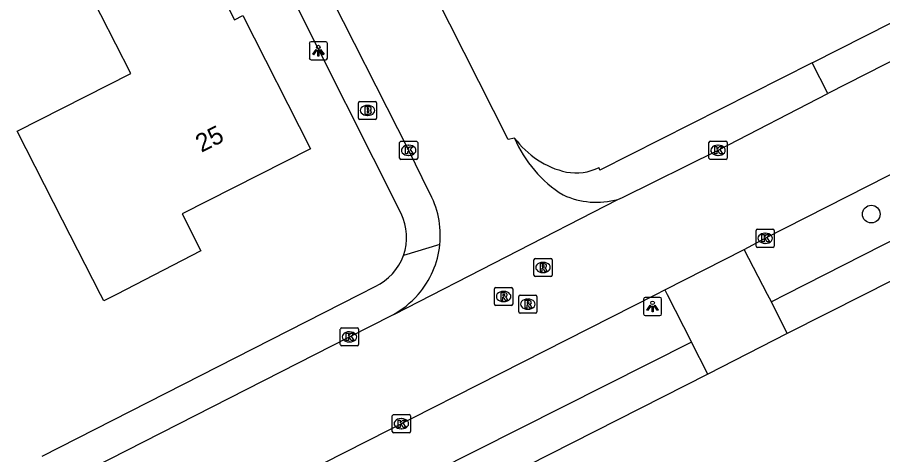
# Model space of a CAD drawing. Extents: x 162722 to 165099, y 384721 to 386283.
# Drawn here: x 164013.51 to 164061.27, y 384991.16 to 385015.28 of the extents above; entities that cross this region are included whole.
import ezdxf

# ---------------------------------------------------------------- set-up
doc = ezdxf.new("R2010")
doc.units = 0
for name, color, linetype in [('IMGEO_Boom', 7, 'Continuous'), ('IMGEO_Brandkraan', 7, 'Continuous'), ('IMGEO_Kolk', 7, 'Continuous'), ('IMGEO_Lichtpunt', 7, 'Continuous'), ('IMGEO_Pand', 7, 'Continuous'), ('IMGEO_Pand_nummerreeks', 7, 'Continuous'), ('IMGEO_Parkeervlak_open', 7, 'Continuous'), ('IMGEO_Rijbaan_lokaal_open', 7, 'Continuous'), ('IMGEO_Rioolput', 7, 'Continuous'), ('IMGEO_Voetpad_open', 7, 'Continuous')]:
    doc.layers.add(name, color=color, linetype=linetype)

msp = doc.modelspace()

# ---------------------------------------------------------------- linework, layer by layer
at = {"layer": 'IMGEO_Boom'}
msp.add_circle((164060.638, 385004.427), 0.489, dxfattribs=at)
at = {"layer": 'IMGEO_Brandkraan'}
for p, q in [((164032.34, 385009.72), (164032.34, 385010.572)), ((164032.415, 385010.646), (164033.267, 385010.646)), ((164032.828, 385010.426), (164032.853, 385010.426)), ((164033.341, 385010.572), (164033.341, 385009.72)), ((164032.851, 385009.866), (164032.826, 385009.866)), ((164033.267, 385009.646), (164032.415, 385009.646))]:
    msp.add_line(p, q, dxfattribs=at)
for points in [[(164032.34, 385009.72), (164032.34, 385010.572)], [(164032.415, 385010.646), (164033.267, 385010.646)], [(164032.688, 385010.346), (164032.688, 385009.946), (164032.901, 385009.946)], [(164032.919, 385010.346), (164032.688, 385010.346)], [(164032.867, 385010.265), (164032.813, 385010.265), (164032.813, 385010.189)], [(164033.341, 385010.572), (164033.341, 385009.72)], [(164032.813, 385010.189), (164032.866, 385010.189)], [(164032.875, 385010.113), (164032.813, 385010.113), (164032.813, 385010.032)], [(164032.813, 385010.032), (164032.875, 385010.032)], [(164033.267, 385009.646), (164032.415, 385009.646)]]:
    msp.add_lwpolyline(points, dxfattribs=at)
for centre, radius, start, end in [((164032.417, 385010.57), 0.0765, 91.552, 178.448), ((164032.417, 385010.57), 0.0765, 91.552, 178.448), ((164032.868, 385010.227), 0.0379, 267.8285, 90.9355), ((164032.923, 385010.201), 0.145, 59.4692, 91.5367), ((164032.948, 385010.248), 0.0922, 285.5137, 58.1501), ((164033.265, 385010.57), 0.0765, 1.552, 88.448), ((164033.265, 385010.57), 0.0765, 1.552, 88.448), ((164032.876, 385010.072), 0.0404, 269.8759, 90.5077), ((164032.907, 385010.197), 0.251, 268.6676, 293.5347), ((164032.953, 385010.056), 0.105, 301.3115, 78.989), ((164032.417, 385009.722), 0.0765, 181.552, 268.448), ((164032.417, 385009.722), 0.0765, 181.552, 268.448), ((164033.265, 385009.722), 0.0765, 271.552, 358.448), ((164033.265, 385009.722), 0.0765, 271.552, 358.448)]:
    msp.add_arc(centre, radius, start, end, dxfattribs=at)
for centre, major_axis, ratio, start_param, end_param in [((164032.827, 385010.146), (-0.387, 0.002), 0.722429, 4.712389, 7.853982), ((164032.852, 385010.146), (-0.39, 0.002), 0.717154, 1.570796, 4.712389)]:
    msp.add_ellipse(centre, major_axis=major_axis, ratio=ratio, start_param=start_param, end_param=end_param, dxfattribs=at)
at = {"layer": 'IMGEO_Kolk'}
for p, q in [((164034.608, 385007.517), (164034.608, 385008.369)), ((164034.683, 385008.443), (164035.535, 385008.443)), ((164035.609, 385008.369), (164035.609, 385007.517)), ((164051.679, 385007.522), (164051.679, 385008.374)), ((164051.754, 385008.448), (164052.606, 385008.448)), ((164052.68, 385008.374), (164052.68, 385007.522)), ((164035.096, 385008.223), (164035.121, 385008.223)), ((164052.167, 385008.228), (164052.192, 385008.228)), ((164035.535, 385007.443), (164034.683, 385007.443)), ((164035.119, 385007.663), (164035.094, 385007.663)), ((164052.606, 385007.448), (164051.754, 385007.448)), ((164052.19, 385007.668), (164052.165, 385007.668)), ((164054.283, 385002.669), (164054.283, 385003.521)), ((164054.358, 385003.595), (164055.21, 385003.595)), ((164055.284, 385003.521), (164055.284, 385002.669)), ((164054.771, 385003.375), (164054.796, 385003.375)), ((164055.21, 385002.595), (164054.358, 385002.595)), ((164054.794, 385002.815), (164054.769, 385002.815)), ((164031.338, 384997.231), (164031.338, 384998.083)), ((164031.413, 384998.157), (164032.265, 384998.157)), ((164031.826, 384997.937), (164031.851, 384997.937)), ((164032.339, 384998.083), (164032.339, 384997.231)), ((164031.849, 384997.377), (164031.824, 384997.377)), ((164032.265, 384997.157), (164031.413, 384997.157)), ((164034.204, 384992.444), (164034.204, 384993.296)), ((164034.279, 384993.37), (164035.131, 384993.37)), ((164034.692, 384993.15), (164034.717, 384993.15)), ((164035.205, 384993.296), (164035.205, 384992.444)), ((164034.715, 384992.59), (164034.69, 384992.59)), ((164035.131, 384992.37), (164034.279, 384992.37))]:
    msp.add_line(p, q, dxfattribs=at)
for points in [[(164034.608, 385007.517), (164034.608, 385008.369)], [(164034.683, 385008.443), (164035.535, 385008.443)], [(164035.609, 385008.369), (164035.609, 385007.517)], [(164051.679, 385007.522), (164051.679, 385008.374)], [(164051.754, 385008.448), (164052.606, 385008.448)], [(164052.68, 385008.374), (164052.68, 385007.522)], [(164034.929, 385008.143), (164035.052, 385008.143), (164035.052, 385007.992), (164035.182, 385008.143), (164035.346, 385008.143), (164035.2, 385007.992), (164035.353, 385007.743), (164035.201, 385007.743), (164035.116, 385007.907), (164035.052, 385007.84), (164035.052, 385007.743), (164034.929, 385007.743), (164034.929, 385008.143)], [(164052, 385008.148), (164052.123, 385008.148), (164052.123, 385007.997), (164052.253, 385008.148), (164052.417, 385008.148), (164052.271, 385007.997), (164052.424, 385007.748), (164052.272, 385007.748), (164052.187, 385007.912), (164052.123, 385007.845), (164052.123, 385007.748), (164052, 385007.748), (164052, 385008.148)], [(164035.535, 385007.443), (164034.683, 385007.443)], [(164052.606, 385007.448), (164051.754, 385007.448)], [(164054.283, 385002.669), (164054.283, 385003.521)], [(164054.358, 385003.595), (164055.21, 385003.595)], [(164055.284, 385003.521), (164055.284, 385002.669)], [(164054.604, 385003.295), (164054.727, 385003.295), (164054.727, 385003.144), (164054.857, 385003.295), (164055.021, 385003.295), (164054.875, 385003.144), (164055.028, 385002.895), (164054.876, 385002.895), (164054.791, 385003.059), (164054.727, 385002.992), (164054.727, 385002.895), (164054.604, 385002.895), (164054.604, 385003.295)], [(164055.21, 385002.595), (164054.358, 385002.595)], [(164031.338, 384997.231), (164031.338, 384998.083)], [(164031.413, 384998.157), (164032.265, 384998.157)], [(164031.659, 384997.857), (164031.782, 384997.857), (164031.782, 384997.706), (164031.912, 384997.857), (164032.076, 384997.857), (164031.93, 384997.706), (164032.083, 384997.457), (164031.931, 384997.457), (164031.846, 384997.621), (164031.782, 384997.554), (164031.782, 384997.457), (164031.659, 384997.457), (164031.659, 384997.857)], [(164032.339, 384998.083), (164032.339, 384997.231)], [(164032.265, 384997.157), (164031.413, 384997.157)], [(164034.204, 384992.444), (164034.204, 384993.296)], [(164034.279, 384993.37), (164035.131, 384993.37)], [(164034.525, 384993.07), (164034.648, 384993.07), (164034.648, 384992.919), (164034.778, 384993.07), (164034.942, 384993.07), (164034.796, 384992.919), (164034.949, 384992.67), (164034.797, 384992.67), (164034.712, 384992.834), (164034.648, 384992.767), (164034.648, 384992.67), (164034.525, 384992.67), (164034.525, 384993.07)], [(164035.205, 384993.296), (164035.205, 384992.444)], [(164035.131, 384992.37), (164034.279, 384992.37)]]:
    msp.add_lwpolyline(points, dxfattribs=at)
for centre, start, end in [((164034.685, 385008.367), 91.552, 178.448), ((164034.685, 385008.367), 91.552, 178.448), ((164035.533, 385008.367), 1.552, 88.448), ((164035.533, 385008.367), 1.552, 88.448), ((164051.756, 385008.372), 91.552, 178.448), ((164051.756, 385008.372), 91.552, 178.448), ((164052.604, 385008.372), 1.552, 88.448), ((164052.604, 385008.372), 1.552, 88.448), ((164034.685, 385007.519), 181.552, 268.448), ((164034.685, 385007.519), 181.552, 268.448), ((164035.533, 385007.519), 271.552, 358.448), ((164035.533, 385007.519), 271.552, 358.448), ((164051.756, 385007.524), 181.552, 268.448), ((164051.756, 385007.524), 181.552, 268.448), ((164052.604, 385007.524), 271.552, 358.448), ((164052.604, 385007.524), 271.552, 358.448), ((164054.36, 385003.519), 91.552, 178.448), ((164054.36, 385003.519), 91.552, 178.448), ((164055.208, 385003.519), 1.552, 88.448), ((164055.208, 385003.519), 1.552, 88.448), ((164054.36, 385002.671), 181.552, 268.448), ((164054.36, 385002.671), 181.552, 268.448), ((164055.208, 385002.671), 271.552, 358.448), ((164055.208, 385002.671), 271.552, 358.448), ((164031.415, 384998.081), 91.552, 178.448), ((164031.415, 384998.081), 91.552, 178.448), ((164032.263, 384998.081), 1.552, 88.448), ((164032.263, 384998.081), 1.552, 88.448), ((164031.415, 384997.233), 181.552, 268.448), ((164031.415, 384997.233), 181.552, 268.448), ((164032.263, 384997.233), 271.552, 358.448), ((164032.263, 384997.233), 271.552, 358.448), ((164034.281, 384993.294), 91.552, 178.448), ((164034.281, 384993.294), 91.552, 178.448), ((164035.129, 384993.294), 1.552, 88.448), ((164035.129, 384993.294), 1.552, 88.448), ((164034.281, 384992.446), 181.552, 268.448), ((164034.281, 384992.446), 181.552, 268.448), ((164035.129, 384992.446), 271.552, 358.448), ((164035.129, 384992.446), 271.552, 358.448)]:
    msp.add_arc(centre, 0.0765, start, end, dxfattribs=at)
for centre, major_axis, ratio, start_param, end_param in [((164035.095, 385007.943), (-0.387, 0.002), 0.722429, 4.712389, 7.853982), ((164035.12, 385007.943), (-0.39, 0.002), 0.717154, 1.570796, 4.712389), ((164052.166, 385007.948), (-0.387, 0.002), 0.722429, 4.712389, 7.853982), ((164052.191, 385007.948), (-0.39, 0.002), 0.717154, 1.570796, 4.712389), ((164054.77, 385003.095), (-0.387, 0.002), 0.722429, 4.712389, 7.853982), ((164054.795, 385003.095), (-0.39, 0.002), 0.717154, 1.570796, 4.712389), ((164031.825, 384997.657), (-0.387, 0.002), 0.722429, 4.712389, 7.853982), ((164031.85, 384997.657), (-0.39, 0.002), 0.717154, 1.570796, 4.712389), ((164034.691, 384992.87), (-0.387, 0.002), 0.722429, 4.712389, 7.853982), ((164034.716, 384992.87), (-0.39, 0.002), 0.717154, 1.570796, 4.712389)]:
    msp.add_ellipse(centre, major_axis=major_axis, ratio=ratio, start_param=start_param, end_param=end_param, dxfattribs=at)
at = {"layer": 'IMGEO_Lichtpunt'}
for p, q in [((164029.628, 385013.842), (164029.628, 385013.035)), ((164029.628, 385013.842), (164029.628, 385013.035)), ((164030.53, 385013.937), (164029.722, 385013.937)), ((164030.53, 385013.937), (164029.722, 385013.937)), ((164030.624, 385013.035), (164030.624, 385013.842)), ((164030.624, 385013.035), (164030.624, 385013.842)), ((164029.722, 385012.941), (164030.53, 385012.941)), ((164029.722, 385012.941), (164030.53, 385012.941)), ((164048.069, 384999.738), (164048.069, 384998.931)), ((164048.069, 384999.738), (164048.069, 384998.931)), ((164048.971, 384999.833), (164048.163, 384999.833)), ((164048.971, 384999.833), (164048.163, 384999.833)), ((164049.065, 384998.931), (164049.065, 384999.738)), ((164049.065, 384998.931), (164049.065, 384999.738)), ((164048.163, 384998.837), (164048.971, 384998.837)), ((164048.163, 384998.837), (164048.971, 384998.837))]:
    msp.add_line(p, q, dxfattribs=at)
for points in [[(164030.002, 385013.506), (164030.041, 385013.478), (164029.853, 385013.216), (164029.815, 385013.243), (164030.002, 385013.506)], [(164030.104, 385013.458), (164030.151, 385013.458), (164030.151, 385013.136), (164030.104, 385013.136), (164030.104, 385013.458)], [(164030.214, 385013.478), (164030.252, 385013.505), (164030.439, 385013.243), (164030.4, 385013.215), (164030.214, 385013.478)], [(164048.443, 384999.402), (164048.482, 384999.374), (164048.294, 384999.112), (164048.256, 384999.139), (164048.443, 384999.402)], [(164048.545, 384999.354), (164048.592, 384999.354), (164048.592, 384999.032), (164048.545, 384999.032), (164048.545, 384999.354)], [(164048.655, 384999.374), (164048.693, 384999.401), (164048.88, 384999.139), (164048.841, 384999.111), (164048.655, 384999.374)]]:
    msp.add_lwpolyline(points, dxfattribs=at)
for centre in [(164030.127, 385013.64), (164048.568, 384999.536)]:
    msp.add_circle(centre, 0.0994, dxfattribs=at)
for centre, start, end in [((164029.722, 385013.842), 90, 180), ((164029.722, 385013.842), 90, 180), ((164030.53, 385013.842), 0, 90), ((164030.53, 385013.842), 0, 90), ((164029.722, 385013.035), 180, 270), ((164029.722, 385013.035), 180, 270), ((164030.53, 385013.035), 270, 0), ((164030.53, 385013.035), 270, 360), ((164048.163, 384999.738), 90, 180), ((164048.163, 384999.738), 90, 180), ((164048.971, 384999.738), 0, 90), ((164048.971, 384999.738), 0, 90), ((164048.163, 384998.931), 180, 270), ((164048.163, 384998.931), 180, 270), ((164048.971, 384998.931), 270, 0), ((164048.971, 384998.931), 270, 360)]:
    msp.add_arc(centre, 0.0946, start, end, dxfattribs=at)
at = {"layer": 'IMGEO_Pand'}
msp.add_lwpolyline([(164015.017, 385021.483), (164020.817, 385024.418), (164023.07, 385019.965), (164025.507, 385015.149), (164025.963, 385015.38), (164029.686, 385008.024), (164022.613, 385004.445), (164023.648, 385002.4), (164018.982, 385000), (164018.286, 384999.642), (164018.104, 385000), (164016.015, 385004.097), (164013.513, 385009.006), (164019.769, 385012.173), (164017.302, 385017.046), (164015.017, 385021.483)], dxfattribs=at)
at = {"layer": 'IMGEO_Parkeervlak_open'}
for points in [[(164034.695, 385004.457), (164028.601, 385016.574)], [(164057.382, 385012.776), (164045.661, 385006.844), (164045.615, 385006.994)], [(164036.828, 385002.748), (164034.821, 385002.15)], [(164014.89, 384991.078), (164032.397, 385000), (164033.264, 385000.442)]]:
    msp.add_lwpolyline(points, dxfattribs=at)
for centre, radius, start, end in [((164044.853, 385011.441), 4.807, 215.8694, 257.5222), ((164044.337, 385009.625), 2.925, 259.7036, 295.9147), ((164032.006, 385003.153), 2.988, 340.3831, 25.8693), ((164032.006, 385003.152), 2.988, 294.8953, 340.4006)]:
    msp.add_arc(centre, radius, start, end, dxfattribs=at)
at = {"layer": 'IMGEO_Rijbaan_lokaal_open'}
for points in [[(164040.957, 385008.624), (164040.599, 385008.534), (164030.122, 385029.274), (164017.119, 385054.888)], [(164036.222, 385005.682), (164035.109, 385007.943), (164030.324, 385017.406)], [(164053.614, 385002.474), (164054.784, 385003.095), (164069.482, 385010.558), (164077.864, 385014.778)], [(164065.538, 385014.795), (164058.234, 385011.087)], [(164046.648, 385005.238), (164046.901, 385005.343), (164052.18, 385007.948), (164058.234, 385011.087)], [(164034.19, 384998.857), (164034.319, 384998.907), (164046.648, 385005.238)], [(164049.239, 385000.247), (164053.614, 385002.474)], [(164025.477, 384988.187), (164048.752, 385000), (164049.239, 385000.247)], [(164015.73, 384989.449), (164016.722, 384989.956), (164031.839, 384997.657), (164034.19, 384998.857)]]:
    msp.add_lwpolyline(points, dxfattribs=at)
for centre, radius, start, end in [((164047.191, 385011.229), 6.757, 202.6778, 238.2417), ((164031.878, 385003.255), 4.976, 354.1493, 29.1907), ((164045.479, 385009.494), 4.414, 245.3069, 285.3579), ((164031.896, 385003.254), 4.958, 318.9875, 354.148), ((164031.881, 385003.267), 4.978, 297.6316, 318.9795)]:
    msp.add_arc(centre, radius, start, end, dxfattribs=at)
at = {"layer": 'IMGEO_Rioolput'}
for p, q in [((164042.022, 385001.059), (164042.022, 385001.911)), ((164042.097, 385001.985), (164042.949, 385001.985)), ((164042.51, 385001.765), (164042.535, 385001.765)), ((164043.023, 385001.911), (164043.023, 385001.059)), ((164042.533, 385001.205), (164042.508, 385001.205)), ((164042.949, 385000.985), (164042.097, 385000.985)), ((164039.849, 384999.457), (164039.849, 385000.309)), ((164039.924, 385000.383), (164040.776, 385000.383)), ((164040.85, 385000.309), (164040.85, 384999.457)), ((164040.337, 385000.163), (164040.362, 385000.163)), ((164041.183, 384999.038), (164041.183, 384999.89)), ((164041.258, 384999.964), (164042.11, 384999.964)), ((164041.671, 384999.744), (164041.696, 384999.744)), ((164042.184, 384999.89), (164042.184, 384999.038)), ((164040.776, 384999.383), (164039.924, 384999.383)), ((164040.36, 384999.603), (164040.335, 384999.603)), ((164042.11, 384998.964), (164041.258, 384998.964)), ((164041.694, 384999.184), (164041.669, 384999.184))]:
    msp.add_line(p, q, dxfattribs=at)
for points in [[(164042.022, 385001.059), (164042.022, 385001.911)], [(164042.097, 385001.985), (164042.949, 385001.985)], [(164042.611, 385001.683), (164042.359, 385001.685), (164042.359, 385001.285)], [(164043.023, 385001.911), (164043.023, 385001.059)], [(164042.359, 385001.285), (164042.483, 385001.285), (164042.483, 385001.447), (164042.494, 385001.447)], [(164042.537, 385001.604), (164042.483, 385001.604), (164042.483, 385001.523)], [(164042.483, 385001.523), (164042.535, 385001.523)], [(164042.541, 385001.418), (164042.612, 385001.285), (164042.752, 385001.285), (164042.687, 385001.411)], [(164042.949, 385000.985), (164042.097, 385000.985)], [(164039.849, 384999.457), (164039.849, 385000.309)], [(164039.924, 385000.383), (164040.776, 385000.383)], [(164040.85, 385000.309), (164040.85, 384999.457)], [(164040.438, 385000.081), (164040.186, 385000.083), (164040.186, 384999.683)], [(164040.186, 384999.683), (164040.31, 384999.683), (164040.31, 384999.845), (164040.321, 384999.845)], [(164040.364, 385000.002), (164040.31, 385000.002), (164040.31, 384999.921)], [(164040.31, 384999.921), (164040.362, 384999.921)], [(164040.368, 384999.816), (164040.439, 384999.683), (164040.579, 384999.683), (164040.514, 384999.809)], [(164041.183, 384999.038), (164041.183, 384999.89)], [(164041.258, 384999.964), (164042.11, 384999.964)], [(164042.184, 384999.89), (164042.184, 384999.038)], [(164040.776, 384999.383), (164039.924, 384999.383)], [(164041.772, 384999.662), (164041.52, 384999.664), (164041.52, 384999.264)], [(164041.52, 384999.264), (164041.644, 384999.264), (164041.644, 384999.426), (164041.655, 384999.426)], [(164041.698, 384999.583), (164041.644, 384999.583), (164041.644, 384999.502)], [(164041.644, 384999.502), (164041.696, 384999.502)], [(164041.702, 384999.397), (164041.773, 384999.264), (164041.913, 384999.264), (164041.848, 384999.39)], [(164042.11, 384998.964), (164041.258, 384998.964)]]:
    msp.add_lwpolyline(points, dxfattribs=at)
for centre, radius, start, end in [((164042.099, 385001.909), 0.0765, 91.552, 178.448), ((164042.099, 385001.909), 0.0765, 91.552, 178.448), ((164042.61, 385001.573), 0.109, 350.3612, 89.416), ((164042.947, 385001.909), 0.0765, 1.552, 88.448), ((164042.947, 385001.909), 0.0765, 1.552, 88.448), ((164042.493, 385001.394), 0.0533, 26.0293, 88.6989), ((164042.519, 385001.712), 0.19, 274.7715, 282.9687), ((164042.543, 385001.508), 0.0964, 77.0061, 93.1865), ((164042.557, 385001.565), 0.0378, 276.6634, 79.6772), ((164042.608, 385001.573), 0.112, 277.5842, 350.9817), ((164042.592, 385001.358), 0.108, 29.5134, 73.7905), ((164042.099, 385001.061), 0.0765, 181.552, 268.448), ((164042.099, 385001.061), 0.0765, 181.552, 268.448), ((164042.947, 385001.061), 0.0765, 271.552, 358.448), ((164042.947, 385001.061), 0.0765, 271.552, 358.448), ((164039.926, 385000.307), 0.0765, 91.552, 178.448), ((164039.926, 385000.307), 0.0765, 91.552, 178.448), ((164040.774, 385000.307), 0.0765, 1.552, 88.448), ((164040.774, 385000.307), 0.0765, 1.552, 88.448), ((164040.32, 384999.792), 0.0533, 26.0293, 88.6989), ((164040.346, 385000.11), 0.19, 274.7715, 282.9687), ((164040.37, 384999.906), 0.0964, 77.0061, 93.1865), ((164040.384, 384999.963), 0.0378, 276.6634, 79.6772), ((164040.437, 384999.971), 0.109, 350.3612, 89.416), ((164040.435, 384999.971), 0.112, 277.5842, 350.9817), ((164040.419, 384999.756), 0.108, 29.5134, 73.7905), ((164041.26, 384999.888), 0.0765, 91.552, 178.448), ((164041.26, 384999.888), 0.0765, 91.552, 178.448), ((164042.108, 384999.888), 0.0765, 1.552, 88.448), ((164042.108, 384999.888), 0.0765, 1.552, 88.448), ((164039.926, 384999.459), 0.0765, 181.552, 268.448), ((164039.926, 384999.459), 0.0765, 181.552, 268.448), ((164040.774, 384999.459), 0.0765, 271.552, 358.448), ((164040.774, 384999.459), 0.0765, 271.552, 358.448), ((164041.654, 384999.373), 0.0533, 26.0293, 88.6989), ((164041.68, 384999.691), 0.19, 274.7715, 282.9687), ((164041.704, 384999.487), 0.0964, 77.0061, 93.1865), ((164041.718, 384999.544), 0.0378, 276.6634, 79.6772), ((164041.771, 384999.552), 0.109, 350.3612, 89.416), ((164041.769, 384999.552), 0.112, 277.5842, 350.9817), ((164041.753, 384999.337), 0.108, 29.5134, 73.7905), ((164041.26, 384999.04), 0.0765, 181.552, 268.448), ((164041.26, 384999.04), 0.0765, 181.552, 268.448), ((164042.108, 384999.04), 0.0765, 271.552, 358.448), ((164042.108, 384999.04), 0.0765, 271.552, 358.448)]:
    msp.add_arc(centre, radius, start, end, dxfattribs=at)
for centre, major_axis, ratio, start_param, end_param in [((164042.509, 385001.485), (-0.387, 0.002), 0.722429, 4.712389, 7.853982), ((164042.534, 385001.485), (-0.39, 0.002), 0.717154, 1.570796, 4.712389), ((164040.336, 384999.883), (-0.387, 0.002), 0.722429, 4.712389, 7.853982), ((164040.361, 384999.883), (-0.39, 0.002), 0.717154, 1.570796, 4.712389), ((164041.67, 384999.464), (-0.387, 0.002), 0.722429, 4.712389, 7.853982), ((164041.695, 384999.464), (-0.39, 0.002), 0.717154, 1.570796, 4.712389)]:
    msp.add_ellipse(centre, major_axis=major_axis, ratio=ratio, start_param=start_param, end_param=end_param, dxfattribs=at)
at = {"layer": 'IMGEO_Voetpad_open'}
for points in [[(164057.382, 385012.776), (164064.675, 385016.487)], [(164058.234, 385011.087), (164057.382, 385012.776)], [(164079.286, 385011.877), (164055.928, 385000), (164055.122, 384999.59)], [(164080.225, 385010.11), (164060.269, 385000), (164056.001, 384997.838)], [(164055.122, 384999.59), (164054.908, 385000), (164053.614, 385002.474)], [(164049.239, 385000.247), (164049.366, 385000), (164050.725, 384997.366)], [(164056.001, 384997.838), (164055.122, 384999.59)], [(164056.001, 384997.838), (164051.623, 384995.596)], [(164050.725, 384997.366), (164026.982, 384985.419)], [(164051.623, 384995.596), (164050.725, 384997.366)], [(164051.623, 384995.596), (164027.937, 384983.596)]]:
    msp.add_lwpolyline(points, dxfattribs=at)

# ---------------------------------------------------------------- texts
at = {"layer": 'IMGEO_Pand_nummerreeks'}
msp.add_text('25', height=1, rotation=26.8373, dxfattribs=at).set_placement((164023.675, 385007.807))

doc.saveas('drawing.dxf')
